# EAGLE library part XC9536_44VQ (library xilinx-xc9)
xc9536_pc44 XC9500 In-System Programmable CPLD Family Auto generated by make-symbol-device-package-bsdl.ulp Rev. 34 Source: xc9536_vq44.bsd
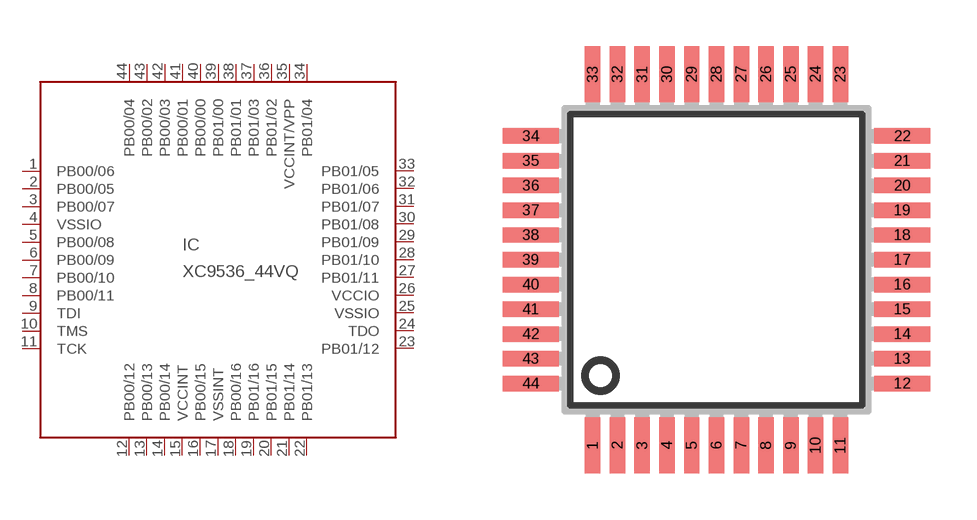
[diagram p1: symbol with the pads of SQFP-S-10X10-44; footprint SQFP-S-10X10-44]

Designator prefix IC

## XC9536_44VQ (MPN: XC9536-15VQG44C; OC_FARNELL: 1193227; OC_NEWARK: 98K3377)  [SQFP-S-10X10-44]
1  PB00/06
2  PB00/05
3  PB00/07
4  VSSIO  pwr
5  PB00/08
6  PB00/09
7  PB00/10
8  PB00/11
9  TDI  in
10  TMS  in
11  TCK  in
12  PB00/12
13  PB00/13
14  PB00/14
15  VCCINT  pwr
16  PB00/15
17  VSSINT  pwr
18  PB00/16
19  PB01/16
20  PB01/15
21  PB01/14
22  PB01/13
23  PB01/12
24  TDO  out
25  VSSIO  pwr
26  VCCIO  pwr
27  PB01/11
28  PB01/10
29  PB01/09
30  PB01/08
31  PB01/07
32  PB01/06
33  PB01/05
34  PB01/04
35  VCCINT/VPP  in
36  PB01/02
37  PB01/03
38  PB01/01
39  PB01/00
40  PB00/00
41  PB00/01
42  PB00/03
43  PB00/02
44  PB00/04

## Footprint SQFP-S-10X10-44 (pad centres in mm)
QFP44 shrink quad flat pack, square
smd 0.5 x 1.8: 1 -4,-6; 2 -3.2,-6; 3 -2.4,-6; 4 -1.6,-6; 5 -0.8,-6; 6 0,-6; 7 0.8,-6; 8 1.6,-6; 9 2.4,-6; 10 3.2,-6; 11 4,-6; 23 4,6; 24 3.2,6; 25 2.4,6; 26 1.6,6; 27 0.8,6; 28 0,6; 29 -0.8,6; 30 -1.6,6; 31 -2.4,6; 32 -3.2,6; 33 -4,6
smd 1.8 x 0.5: 12 6,-4; 13 6,-3.2; 14 6,-2.4; 15 6,-1.6; 16 6,-0.8; 17 6,0; 18 6,0.8; 19 6,1.6; 20 6,2.4; 21 6,3.2; 22 6,4; 34 -6,4; 35 -6,3.2; 36 -6,2.4; 37 -6,1.6; 38 -6,0.8; 39 -6,0; 40 -6,-0.8; 41 -6,-1.6; 42 -6,-2.4; 43 -6,-3.2; 44 -6,-4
